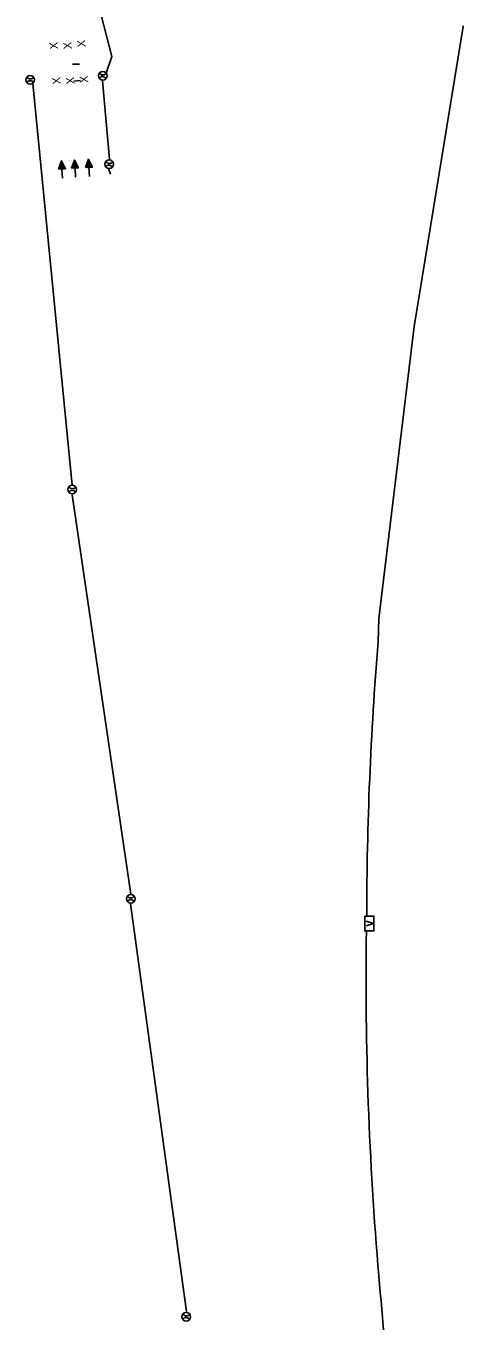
# Model space of a CAD drawing. Extents: x 601562 to 605316, y 332050 to 402250.
# Drawn here: x 602622 to 603001, y 364502 to 365625 of the extents above; entities that cross this region are included whole.
import ezdxf

# ---------------------------------------------------------------- set-up
doc = ezdxf.new("R2010")
doc.units = 0
for name, color, linetype in [('Default', 7, 'Continuous'), ('P_FTMS', 7, 'Continuous'), ('P_FTMSConduit', 7, 'Continuous')]:
    doc.layers.add(name, color=color, linetype=linetype)

# ---------------------------------------------------------------- blocks, each defined once
blk = doc.blocks.new('FTMS_FCV')
at = {"layer": 'P_FTMS'}
blk.add_line((12.7, 16.3), (0.6, -21.9), dxfattribs=at)
blk.add_lwpolyline([(39.1, 24.4), (-39.1, 24.4), (-39.1, -24.4), (39.1, -24.4)], close=True, dxfattribs=at)
blk.add_lwpolyline([(-12.1, 16.2), (0.6, -21.9)], dxfattribs=at)
blk = doc.blocks.new('POINT_DISPLAY')
at = {"layer": 'Default'}
blk.add_line((0, 0), (0, 0), dxfattribs=at)

msp = doc.modelspace()

# ---------------------------------------------------------------- linework, layer by layer
at = {"layer": 'P_FTMS'}
for p, q in [((602650.6, 365501.4), (602654.4, 365505.7)), ((602650.7, 365501.2), (602654.5, 365505.5)), ((602650.8, 365502), (602654.3, 365505.9)), ((602651, 365502.6), (602654.1, 365506.2)), ((602651.1, 365501.2), (602654.6, 365505.2)), ((602651.2, 365503.3), (602654, 365506.4)), ((602651.2, 365503.3), (602653.4, 365501.4)), ((602651.3, 365503.5), (602653.8, 365501.4)), ((602651.4, 365501.2), (602654.7, 365505)), ((602651.4, 365503.8), (602654.1, 365501.4)), ((602651.5, 365503.9), (602653.9, 365506.7)), ((602651.5, 365504), (602654.5, 365501.4)), ((602651.6, 365504.3), (602654.8, 365501.4)), ((602651.7, 365504.6), (602653.8, 365506.9)), ((602651.7, 365504.6), (602655.2, 365501.5)), ((602651.8, 365504.8), (602655.5, 365501.5)), ((602651.8, 365501.3), (602654.9, 365504.7)), ((602651.9, 365505.2), (602653.7, 365507.1)), ((602651.9, 365505.1), (602655.9, 365501.5)), ((602652, 365505.3), (602656.2, 365501.5)), ((602652.1, 365505.8), (602653.5, 365507.4)), ((602652.1, 365505.8), (602656.1, 365502.3)), ((602652.1, 365505.6), (602656.4, 365501.7)), ((602652.1, 365501.3), (602655, 365504.5)), ((602652.2, 365506.1), (602655.8, 365502.9)), ((602652.3, 365506.3), (602655.5, 365503.5)), ((602652.4, 365506.5), (602653.4, 365507.6)), ((602652.4, 365506.6), (602655.2, 365504.1)), ((602652.5, 365506.8), (602654.9, 365504.7)), ((602652.5, 365501.3), (602655.1, 365504.3)), ((602652.6, 365507.1), (602653.3, 365507.9)), ((602652.6, 365507.1), (602654.6, 365505.3)), ((602652.7, 365507.3), (602654.3, 365505.9)), ((602652.8, 365507.7), (602653.2, 365508.1)), ((602652.8, 365507.6), (602654, 365506.5)), ((602652.8, 365501.3), (602655.2, 365504)), ((602652.9, 365507.8), (602653.7, 365507.1)), ((602653, 365508.1), (602653.4, 365507.8)), ((602653.2, 365501.3), (602655.4, 365503.8)), ((602653.6, 365501.4), (602655.5, 365503.5)), ((602653.9, 365501.4), (602655.6, 365503.3)), ((602661.9, 365502.1), (602665.7, 365506.5)), ((602662, 365502), (602665.8, 365506.2)), ((602662.1, 365502.8), (602665.6, 365506.7)), ((602662.3, 365503.4), (602665.5, 365506.9)), ((602662.3, 365503.3), (602663.7, 365502.1)), ((602662.4, 365502), (602665.9, 365506)), ((602662.4, 365503.5), (602664, 365502.1)), ((602662.5, 365503.8), (602664.4, 365502.1)), ((602662.6, 365504), (602665.3, 365507.2)), ((602662.6, 365504.3), (602665.1, 365502.1)), ((602662.6, 365504), (602664.7, 365502.1)), ((602662.7, 365502), (602666.1, 365505.7)), ((602662.7, 365504.5), (602665.4, 365502.2)), ((602662.8, 365504.7), (602665.2, 365507.4)), ((602662.8, 365504.8), (602665.8, 365502.2)), ((602662.9, 365505.1), (602666.1, 365502.2)), ((602663, 365505.3), (602665.1, 365507.7)), ((602663, 365505.3), (602666.5, 365502.2)), ((602663.1, 365505.6), (602666.8, 365502.2)), ((602663.1, 365502), (602666.2, 365505.5)), ((602663.2, 365505.9), (602665, 365507.9)), ((602663.2, 365505.8), (602667.2, 365502.3)), ((602663.3, 365506.1), (602667.5, 365502.3)), ((602663.4, 365506.3), (602667.7, 365502.5)), ((602663.5, 365506.6), (602664.9, 365508.1)), ((602663.5, 365506.6), (602667.4, 365503.1)), ((602663.5, 365502), (602666.3, 365505.3)), ((602663.6, 365507.1), (602666.8, 365504.3)), ((602663.6, 365506.8), (602667.1, 365503.7)), ((602663.7, 365507.2), (602664.7, 365508.4)), ((602663.7, 365507.3), (602666.5, 365504.9)), ((602663.8, 365507.6), (602666.2, 365505.5)), ((602663.8, 365502.1), (602666.4, 365505)), ((602663.9, 365507.8), (602664.6, 365508.6)), ((602663.9, 365507.8), (602665.9, 365506.1)), ((602664, 365508.1), (602665.6, 365506.7)), ((602664.1, 365508.5), (602664.5, 365508.9)), ((602664.1, 365508.4), (602665.3, 365507.3)), ((602664.2, 365508.6), (602665, 365507.9)), ((602664.2, 365502.1), (602666.5, 365504.8)), ((602664.3, 365508.9), (602664.7, 365508.5)), ((602664.5, 365502.1), (602666.7, 365504.5)), ((602664.9, 365502.1), (602666.8, 365504.3)), ((602665.2, 365502.1), (602666.9, 365504.1)), ((602665.6, 365502.2), (602667, 365503.8)), ((602665.9, 365502.2), (602667.1, 365503.6)), ((602666.3, 365502.2), (602667.3, 365503.3)), ((602674, 365502.8), (602677.8, 365507.1)), ((602674.2, 365503.4), (602677.7, 365507.4)), ((602674.2, 365502.6), (602678, 365506.9)), ((602674.2, 365503.4), (602675.1, 365502.7)), ((602674.3, 365503.7), (602675.5, 365502.7)), ((602674.4, 365503.9), (602675.8, 365502.7)), ((602674.5, 365504.1), (602677.6, 365507.6)), ((602674.5, 365502.6), (602678.1, 365506.6)), ((602674.5, 365504.2), (602676.2, 365502.7)), ((602674.6, 365504.4), (602676.5, 365502.8)), ((602674.7, 365504.7), (602677.5, 365507.8)), ((602674.7, 365504.7), (602676.9, 365502.8)), ((602674.8, 365504.9), (602677.2, 365502.8)), ((602674.9, 365505.3), (602677.4, 365508.1)), ((602674.9, 365502.7), (602678.2, 365506.4)), ((602674.9, 365505.2), (602677.6, 365502.8)), ((602675, 365505.5), (602677.9, 365502.8)), ((602675.1, 365505.7), (602678.3, 365502.9)), ((602675.2, 365506), (602677.2, 365508.3)), ((602675.2, 365506.2), (602679, 365502.9)), ((602675.2, 365502.7), (602678.3, 365506.2)), ((602675.2, 365506), (602678.6, 365502.9)), ((602675.3, 365506.5), (602679.3, 365502.9)), ((602675.4, 365506.6), (602677.1, 365508.6)), ((602675.4, 365506.7), (602679.7, 365502.9)), ((602675.5, 365507), (602679.8, 365503.2)), ((602675.6, 365507.2), (602677, 365508.8)), ((602675.6, 365507.2), (602679.5, 365503.8)), ((602675.6, 365502.7), (602678.5, 365505.9)), ((602675.7, 365507.5), (602679.2, 365504.4)), ((602675.8, 365507.9), (602676.9, 365509)), ((602675.8, 365507.7), (602678.9, 365505)), ((602675.9, 365508), (602678.6, 365505.6)), ((602676, 365508.2), (602678.3, 365506.2)), ((602676, 365502.7), (602678.6, 365505.7)), ((602676.1, 365508.5), (602676.8, 365509.3)), ((602676.1, 365508.5), (602678, 365506.8)), ((602676.2, 365509), (602677.4, 365508)), ((602676.2, 365508.8), (602677.7, 365507.4)), ((602676.3, 365509.1), (602676.6, 365509.5)), ((602676.3, 365509.3), (602677.1, 365508.6)), ((602676.3, 365502.7), (602678.7, 365505.4)), ((602676.4, 365509.5), (602676.8, 365509.2)), ((602676.7, 365502.8), (602678.8, 365505.2)), ((602677, 365502.8), (602678.9, 365505)), ((602677.4, 365502.8), (602679.1, 365504.7)), ((602677.7, 365502.8), (602679.2, 365504.5)), ((602678.1, 365502.8), (602679.3, 365504.2)), ((602678.4, 365502.9), (602679.4, 365504)), ((602678.8, 365502.9), (602679.5, 365503.8)), ((602679.1, 365502.9), (602679.7, 365503.5)), ((602679.5, 365502.9), (602679.8, 365503.3)), ((602650.5, 365501.3), (602650.6, 365501.2)), ((602650.6, 365501.5), (602650.9, 365501.2)), ((602650.7, 365501.8), (602651.3, 365501.2)), ((602650.8, 365502), (602651.6, 365501.3)), ((602650.9, 365502.3), (602652, 365501.3)), ((602651, 365502.5), (602652.4, 365501.3)), ((602651.1, 365503), (602653.1, 365501.3)), ((602651.1, 365502.8), (602652.7, 365501.3)), ((602654, 365493.4), (602653.5, 365501.4)), ((602654.3, 365501.4), (602655.7, 365503.1)), ((602654.6, 365501.4), (602655.8, 365502.8)), ((602655, 365501.5), (602656, 365502.6)), ((602655.3, 365501.5), (602656.1, 365502.3)), ((602655.7, 365501.5), (602656.2, 365502.1)), ((602656, 365501.5), (602656.3, 365501.9)), ((602656.4, 365501.5), (602656.4, 365501.6)), ((602661.8, 365502), (602661.9, 365501.9)), ((602661.9, 365502.3), (602662.3, 365502)), ((602662, 365502.5), (602662.6, 365502)), ((602662.1, 365502.8), (602663, 365502)), ((602662.2, 365503), (602663.3, 365502)), ((602665.3, 365494.2), (602664.8, 365502.1)), ((602666.6, 365502.2), (602667.4, 365503.1)), ((602667, 365502.3), (602667.5, 365502.9)), ((602667.3, 365502.3), (602667.6, 365502.6)), ((602667.7, 365502.3), (602667.8, 365502.4)), ((602674, 365502.7), (602674, 365502.6)), ((602674.1, 365502.9), (602674.4, 365502.6)), ((602674.2, 365503.2), (602674.8, 365502.6)), ((602677.4, 365494.8), (602676.9, 365502.8)), ((602679.8, 365503), (602679.9, 365503))]:
    msp.add_line(p, q, dxfattribs=at)
for points in [[(602650.5, 365501.2), (602653.1, 365508.4), (602656.5, 365501.5)], [(602661.8, 365501.9), (602664.4, 365509.1), (602667.8, 365502.3)], [(602673.9, 365502.6), (602676.5, 365509.8), (602679.9, 365503)]]:
    msp.add_lwpolyline(points, close=True, dxfattribs=at)
for centre in [(602626, 365578.6), (602688.8, 365582.2), (602694.4, 365505.4), (602662.4, 365223.3), (602713.1, 364868.5), (602761.2, 364506.1)]:
    msp.add_circle(centre, 3.75, dxfattribs=at)
for centre, start, end in [((602688.9, 365586.7), 214.9369, 321.1925), ((602625.9, 365574.1), 34.9369, 141.1925), ((602626.2, 365583.1), 214.9369, 321.1925), ((602688.6, 365577.7), 34.9369, 141.1925), ((602694.1, 365500.9), 32.6299, 138.8855), ((602694.7, 365509.9), 212.6299, 318.8855), ((602662.2, 365218.8), 34.9369, 141.1925), ((602662.5, 365227.8), 214.9369, 321.1925), ((602712.9, 364864), 34.9369, 141.1925), ((602713.2, 364873), 214.9369, 321.1925), ((602761, 364501.6), 34.9369, 141.1925), ((602761.3, 364510.6), 214.9369, 321.1925)]:
    msp.add_arc(centre, 3.75, start, end, dxfattribs=at)
at = {"layer": 'P_FTMSConduit'}
for p, q in [((602696.8, 365598.9), (602685.2, 365643.7)), ((602691.9, 365584.3), (602696.8, 365598.9)), ((602668.7, 365592.2), (602662.7, 365592.1)), ((602628.3, 365575.5), (602662.2, 365227.2)), ((602663.7, 365577.5), (602669.6, 365578.1)), ((602694.7, 365509.9), (602688.6, 365577.7)), ((602693.8, 365501.7), (602695.6, 365496.7)), ((602662.2, 365218.8), (602713.1, 364872.5)), ((602712.9, 364864), (602761.3, 364510.6))]:
    msp.add_line(p, q, dxfattribs=at)
msp.add_lwpolyline([(603001, 365625.4), (603001, 365625), (602958.5, 365364.7), (602928.1, 365111.6), (602927.4, 365091.2)], dxfattribs=at)
for centre, radius, start, end in [((605889.6, 364848.5), 2972.1, 175.3176, 179.9052), ((605900.4, 364798), 2983.4, 179.1815, 184.9317), ((617011.1, 365756.7), 14135.4, 184.93174, 185.86941)]:
    msp.add_arc(centre, radius, start, end, dxfattribs=at)

# ---------------------------------------------------------------- block references
at = {"layer": 'P_FTMS'}
for name, p, xscale, yscale, rotation in [('POINT_DISPLAY', (602653.1, 365508.4), 0.32808333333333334, 0.32808333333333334, 119.40954798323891), ('POINT_DISPLAY', (602664.4, 365509.1), 0.32808333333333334, 0.32808333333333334, 119.40954798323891), ('POINT_DISPLAY', (602676.5, 365509.8), 0.32808333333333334, 0.32808333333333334, 119.40954798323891), ('FTMS_FCV', (602919.8, 364847), 0.16404166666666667, 0.16404166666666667, 90.21124366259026)]:
    msp.add_blockref(name, p, dxfattribs=dict(at, xscale=xscale, yscale=yscale, rotation=rotation))

# ---------------------------------------------------------------- texts
at = {"layer": 'P_FTMSConduit'}
for p in [(602650.1, 365605.4), (602662.1, 365605.5), (602674, 365607.2), (602676.3, 365576.2), (602652.4, 365575), (602664.4, 365575.1)]:
    msp.add_text('X', height=7, rotation=94.7776, dxfattribs=at).set_placement(p)

doc.saveas('drawing.dxf')
